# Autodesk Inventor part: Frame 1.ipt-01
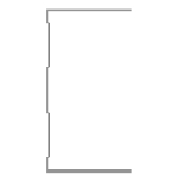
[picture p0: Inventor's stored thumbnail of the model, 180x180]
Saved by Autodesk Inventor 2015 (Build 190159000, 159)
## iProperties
_CCFamilyMember: 1
_CCFamilyDisplayName: Kévin - Kévin Novo
_FrameMemberDoc: Frame Member File
_Version: 15.0.0
_GetPNFromCC: 1
Created: 2015-04
Part Number: Frame 1.ipt-01
Material: Aluminum 6061
Description: Kévin Novo
Document SubType Name: Modeling
Standard: Kevin
Designer: suporte
Standards Organization: Kevin
Language: en-US
Size Designation: (Unnamed 1)
Categories: <MemberInstance><Categories><Category DisplayName="Structural Shapes" InternalName="089c4875-fa83-4c05-b084-43b9cc11f5ed" Mnemonic="GRDR"><CategoryParameter Dis
Density: 2.7 g/cm^3
Appearance: Aluminum - Flat
IsCustomPart: 1
G_L: 1498,590 mm
G_W: 50,000 mm
G_H: 75,000 mm
+E6FCAD43-AC47-4BE5-B588-6C7439B0D930+CUTDETAIL1: Cut
+70689007-2E59-4765-8830-24DCB7203E4C+CUTDETAIL2: Cut
Author: suporte
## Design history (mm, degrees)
node "Start Plane"
node "End Plane"
sketch "Sketch"
  geometry: L1 (24.7, 37.5)-(24.7, 36.9); L2 (24.7, 36.9)-(-24.7, 36.9); L3 (-24.7, -36.9)-(24.7, -36.9); L4 (24.7, -36.9)-(24.7, -37.5); L5 (24.7, -37.5)-(-25.3, -37.5); L6 (-25.3, 37.5)-(24.7, 37.5); L7 (-24.7, 36.9)-(-24.7, 31.9); L8 (-24.7, 31.9)-(-23.3, 30.5); L9 (-23.3, 30.5)-(-23.3, 10.934); L10 (-23.3, 10.934)-(-24.7, 9.534); L11 (-24.7, 9.534)-(-24.7, -9.534); L12 (-24.7, -9.534)-(-23.3, -10.934); L13 (-23.3, -10.934)-(-23.3, -30.5); L14 (-23.3, -30.5)-(-24.7, -31.9); L15 (-24.7, -31.9)-(-24.7, -36.9); L16 (-25.3, -37.5)-(-25.3, -31.651); L17 (-25.3, -31.651)-(-23.9, -30.251); L18 (-23.9, -30.251)-(-23.9, -11.183); L19 (-23.9, -11.183)-(-25.3, -9.783); L20 (-25.3, -9.783)-(-25.3, 9.783); L21 (-25.3, 9.783)-(-23.9, 11.183); L22 (-23.9, 11.183)-(-23.9, 30.251); L23 (-23.9, 30.251)-(-25.3, 31.651); L24 (-25.3, 31.651)-(-25.3, 37.5); L25 (-25.3, 0)-(30.37, 0); 3 further points
  constraints: 50 end point, 10 point on line, 9 parallel, 5 perpendicular, 4 equal length, 3 midpoint, 3 vertical, 2 vertical alignment, 1 collinear, 1 horizontal, 1 horizontal alignment
  dimensions: "d3" = 0.6 distance of L1.start L1.end (= d6); "d5" = 75 distance between parallel lines of L5 L6; "d6" = 0.6 distance between parallel lines of L24 L7 (= d8); "d7" = 0.6 distance between parallel lines of L8 L23 (= d8); "d8" = 0.6 distance between parallel lines of L22 L9 (= d12); "Espessura" = 0.6 distance between parallel lines of L17 L14; "d10" = 0.6 distance between parallel lines of L13 L18 (= Espessura); "d11" = 0.6 distance between parallel lines of L12 L19 (= Espessura); "d12" = 0.6 distance between parallel lines of L21 L10 (= d11); "d13" = 5 distance of L2.end L7.end; "d15" = 135 deg angle of L9 L8; "d16" = 2 distance between parallel lines of L24 L9; "d17" = 50 distance of L6.start L1.start
extrude "Body" join sketch "Sketch" stored distance "d24" = 0.13; taper "d25" = 0 deg
node "Driven Length"
  sketch "Sketch10"
    geometry: L1 (0, 0)-(10, 0) reference
    constraints: 2 end point, 1 horizontal
  workplane "Work Plane7"
  sketch "Sketch11"
    geometry: L1 (-2, -798.826)-(12, -798.826) reference; L2 (-2, 699.763)-(12, 699.763) reference
    dimensions: "d27" = 1498.58967 distance between parallel lines of L1 L2 (derived)
workplane "Work Plane8"
split "Split1"
workplane "Work Plane9"
split "Split2"
body "Solid1"
other parameters: "tamanho" = 724.76332, "G_OFFSET_START" = 798.82636 [user parameter; used in 1 equation term], "G_OFFSET_END" = -25 [user parameter; used in 1 equation term], "d22" = -798.82636 (= -G_OFFSET_START), "d23" = 699.76332 (= tamanho + G_OFFSET_END), "G_L" = 1498.58967 (= d27) [user parameter], "d34" = 90 deg
